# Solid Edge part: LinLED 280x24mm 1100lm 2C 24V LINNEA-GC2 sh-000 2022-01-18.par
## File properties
Author: robert.pupel
Template: iso metric part.par
Last saved by: robert.pupel
Revision: 2
Application: Solid Edge
Gęstość: 0.000 kg/m^3
Dokładność: 0.990
Username: robert.pupel
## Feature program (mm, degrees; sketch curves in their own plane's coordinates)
base feature "unnamed BaseFeature 1"
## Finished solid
Body 1: solid body, 958 faces, 2482 edges, 1588 vertices, 3 separate solids.
  Faces by surface: plane 648, cylinder 150, spline 96, cone 30, sphere 16, torus 10, spun 8
  Edges by curve: line 1826, curve on surface 324, circle 212, ellipse 66, spline 50, intersection 4
Bounding box of the edges (mm; curved faces can reach further): 279.500 x 4.500 x 23.800, from (-139.75, -3.5, -11.1504) to (139.75, 1, 12.6496).
Cylindrical faces by radius (mm): R0.2 x46, R0.2169 x6, R0.25 x20, R0.3373 x6, R0.4 x8, R0.4006 x2, R0.4008 x2, R0.525 x2, R0.6 x20, R1 x16, R1.1 x4, R1.2 x10, R2.15 x8
Conical faces (half-angle, radius in mm at the cone's reference point): 0.5 deg R0.5056 x4, 0.5 deg R1.0082 x4, 1 deg R0.5511 x2, 10 deg R0.2132 x4, 10 deg R0.4132 x4, 18.8604 deg R1.0669 x4, 27.363 deg R0.6214 x2, 45 deg R0.575 x2, 45 deg R0.625 x4
Toroidal faces (ring radius, tube radius in mm): R0.8 r0.2 x4, R0.8522 r0.3 x2, R0.9002 r0.2 x2, R0.9018 r0.2 x2
Spherical faces by radius (mm): R0.2 x12, R0.6 x4
Planar faces by outward normal: +x 74, +y 13, +z 98, -x 74, -y 97, -z 76, oblique 216
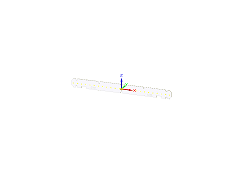
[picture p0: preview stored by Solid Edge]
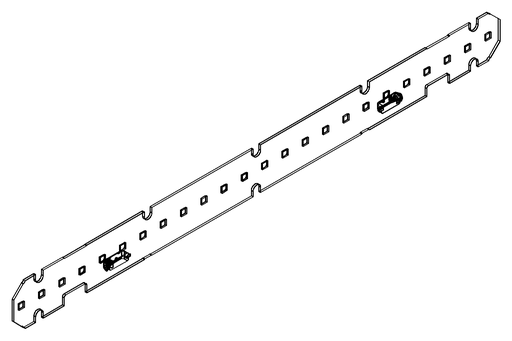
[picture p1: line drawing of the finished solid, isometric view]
